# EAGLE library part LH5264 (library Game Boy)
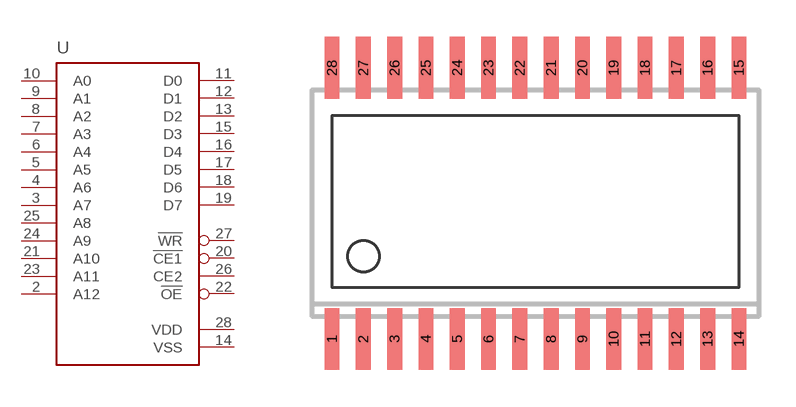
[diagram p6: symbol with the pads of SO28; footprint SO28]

Designator prefix -

## LH5264  [SO28]
2  A12  in
3  A7  in
4  A6  in
5  A5  in
6  A4  in
7  A3  in
8  A2  in
9  A1  in
10  A0  in
11  D0
12  D1
13  D2
14  VSS  pwr
15  D3
16  D4
17  D5
18  D6
19  D7
20  !CE1  in
21  A10  in
22  !OE  in
23  A11  in
24  A9  in
25  A8  in
26  CE2  in
27  !WR  in
28  VDD  pwr

## Footprint SO28 (pad centres in mm)
smd 0.6 x 2.5: 1 -8.255,-5.5; 2 -6.985,-5.5; 3 -5.715,-5.5; 4 -4.445,-5.5; 5 -3.175,-5.5; 6 -1.905,-5.5; 7 -0.635,-5.5; 8 0.635,-5.5; 9 1.905,-5.5; 10 3.175,-5.5; 11 4.445,-5.5; 12 5.715,-5.5; 13 6.985,-5.5; 14 8.255,-5.5; 15 8.255,5.5; 16 6.985,5.5; 17 5.715,5.5; 18 4.445,5.5; 19 3.175,5.5; 20 1.905,5.5; 21 0.635,5.5; 22 -0.635,5.5; 23 -1.905,5.5; 24 -3.175,5.5; 25 -4.445,5.5; 26 -5.715,5.5; 27 -6.985,5.5; 28 -8.255,5.5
